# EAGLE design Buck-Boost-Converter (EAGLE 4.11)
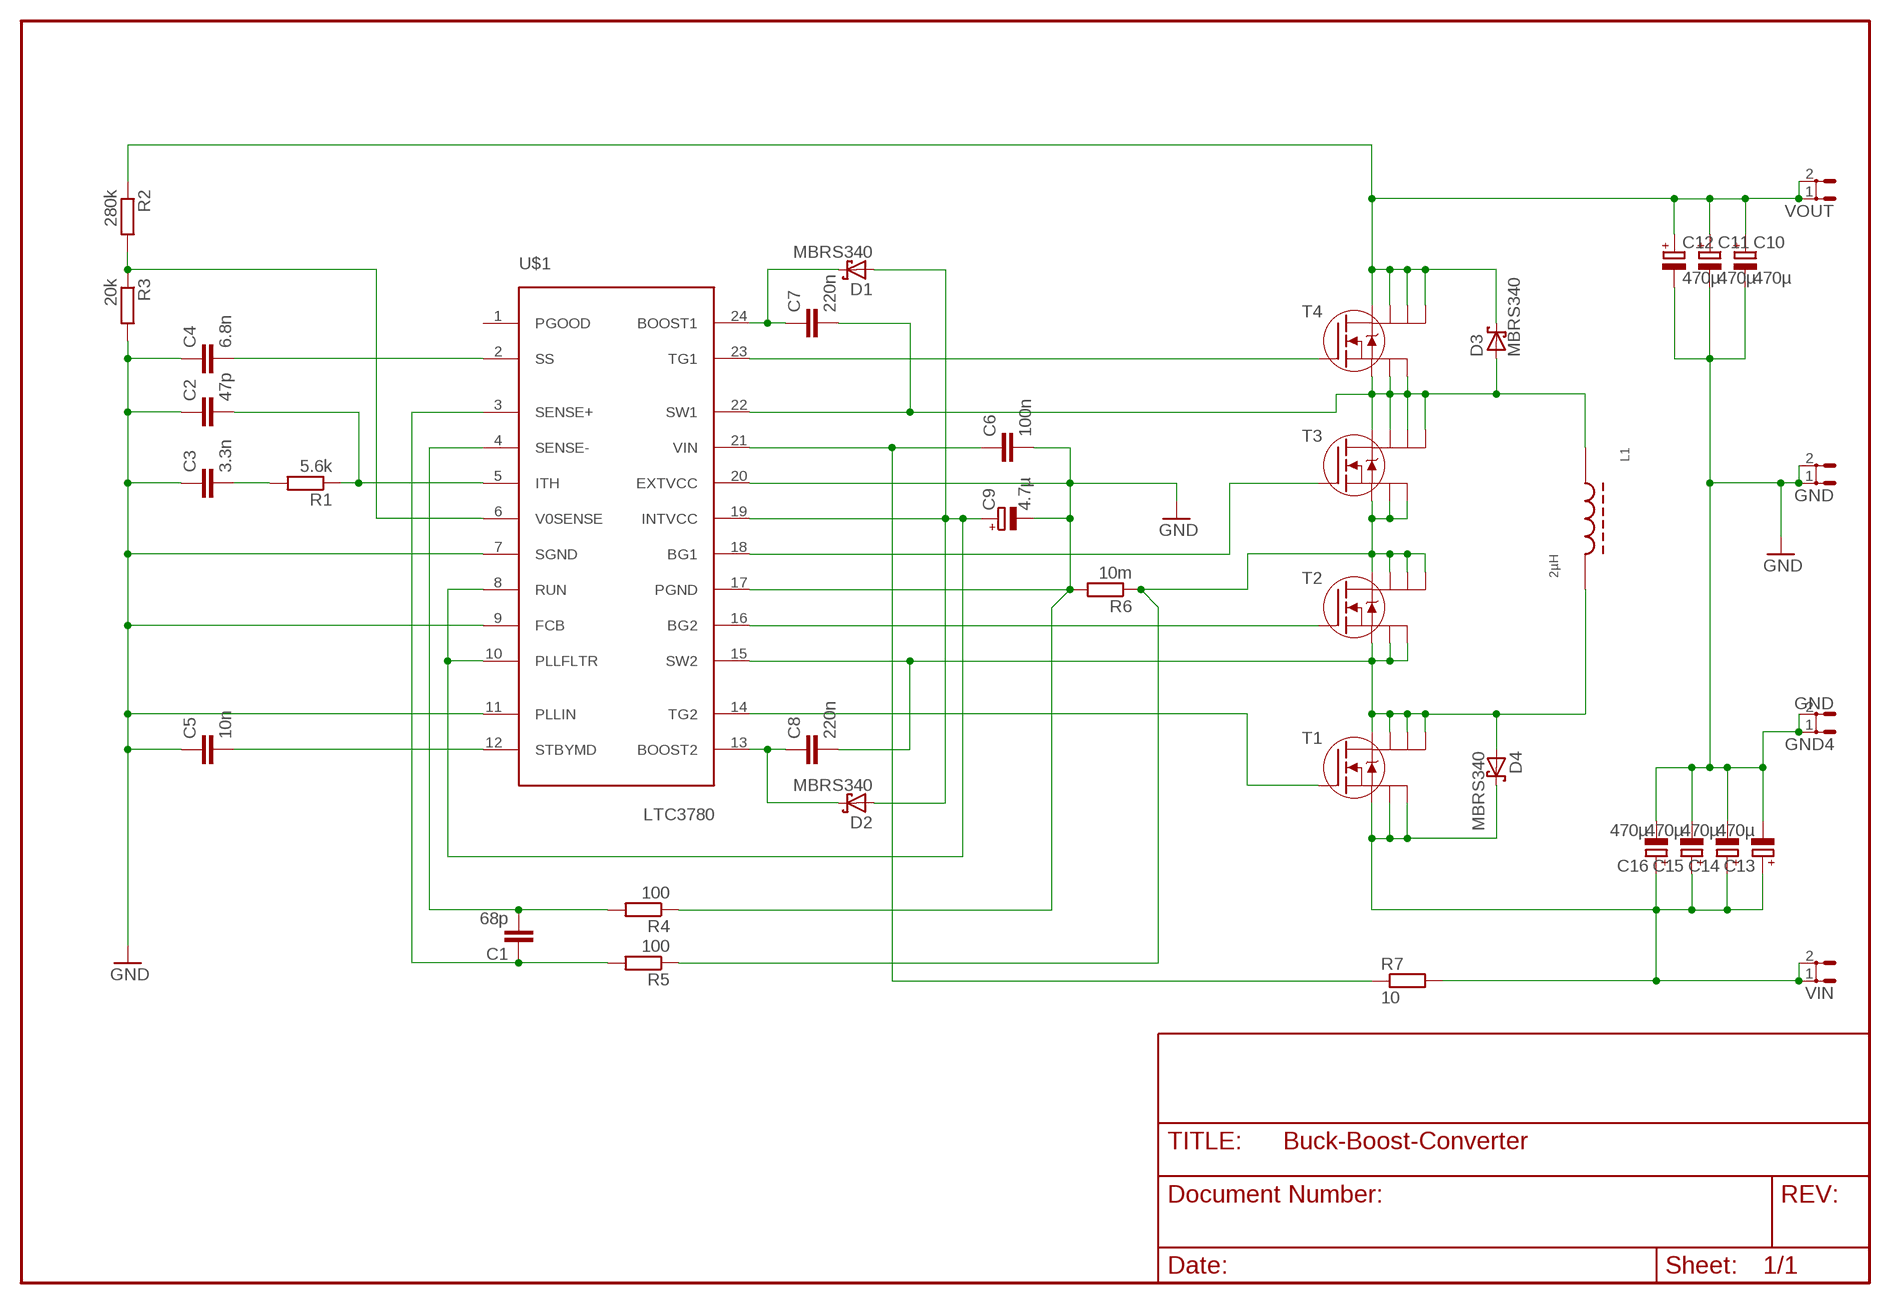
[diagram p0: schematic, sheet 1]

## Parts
C1  68p  C-EUC0805  [C0805]
C2  47p  C-EUC0805  [C0805]
C3  3.3n  C-EUC0805  [C0805]
C4  6.8n  C-EUC0805  [C0805]
C5  10n  C-EUC0805  [C0805]
C6  100n  C-EUC0805  [C0805]
C7  220n  C-EUC1812  [C1812]
C8  220n  C-EUC1812  [C1812]
C9  4.7µ  CPOL-EUD/7343-31R  [D/7343-31R]
C10  470µ  CPOL-EUE5-13  [E5-13]
C11  470µ  CPOL-EUE5-13  [E5-13]
C12  470µ  CPOL-EUE5-13  [E5-13]
C13  470µ  CPOL-EUE5-13  [E5-13]
C14  470µ  CPOL-EUE5-13  [E5-13]
C15  470µ  CPOL-EUE5-13  [E5-13]
C16  470µ  CPOL-EUE5-13  [E5-13]
D1  MBRS340  [SMC]
D2  MBRS340  [SMC]
D3  MBRS340  [SMC]
D4  MBRS340  [SMC]
GND  ST6,3  [ST6,3]
GND4  GND  ST6,3  [ST6,3]
L1  2µH  SER2000  [SER2000]
R1  5.6k  R-EU_R0805  [R0805]
R2  280k  R-EU_R0805  [R0805]
R3  20k  R-EU_R0805  [R0805]
R4  100  R-EU_R0805  [R0805]
R5  100  R-EU_R0805  [R0805]
R6  10m  R-EU_0207/7  [0207/7]
R7  10  R-EU_R1206  [R1206]
T1  IRF7413  [SO8-2]
T2  IRF7413  [SO8-2]
T3  IRF7413  [SO8-2]
T4  IRF7413  [SO8-2]
U$1  LTC3780  [SSOP24]
VIN  ST6,3  [ST6,3]
VOUT  ST6,3  [ST6,3]

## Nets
GND [Power]: C2.1 C3.1 C4.1 C5.1 C6.2 C9.- C10.- C11.- C12.- C13.- C14.- C15.- C16.- GND4.1 GND4.2 GND.1 GND.2 R3.2 R4.1 R6.2 U$1.7(SGND) U$1.9(FCB) U$1.11(PLLIN) U$1.17(PGND) U$1.20(EXTVCC)
N$1: T1.4(G) U$1.14(TG2)
N$2: T2.4(G) U$1.16(BG2)
N$3: T3.4(G) U$1.18(BG1)
N$4: T4.4(G) U$1.23(TG1)
N$5: C9.+ D1.A D2.A U$1.8(RUN) U$1.10(PLLFLTR) U$1.19(INTVCC)
N$7: C7.2 D3.A L1.1 T3.5(D) T3.6(D) T3.7(D) T3.8(D) T4.1(S) T4.2(S) T4.3(S) U$1.22(SW1)
N$8: C1.2 R4.2 U$1.4(SENSE-)
N$10: C1.1 R5.2 U$1.3(SENSE+)
N$11: C4.2 U$1.2(SS)
N$12: C2.2 R1.1 U$1.5(ITH)
N$13: C8.2 D4.A L1.2 T1.5(D) T1.6(D) T1.7(D) T1.8(D) T2.1(S) T2.2(S) T2.3(S) U$1.15(SW2)
N$14: C3.2 R1.2
N$15: R2.2 R3.1 U$1.6(V0SENSE)
N$16 [Power]: R5.1 R6.1 T2.5(D) T2.6(D) T2.7(D) T2.8(D) T3.1(S) T3.2(S) T3.3(S)
N$17: C7.1 D1.C U$1.24(BOOST1)
N$18: C5.2 U$1.12(STBYMD)
N$19: C8.1 D2.C U$1.13(BOOST2)
N$21: C6.1 R7.1 U$1.21(VIN)
N$22 [Power]: C10.+ C11.+ C12.+ D3.C R2.1 T4.5(D) T4.6(D) T4.7(D) T4.8(D) VOUT.1 VOUT.2
N$28: C13.+ C14.+ C15.+ C16.+ D4.C R7.2 T1.1(S) T1.2(S) T1.3(S) VIN.1 VIN.2
Unconnected: U$1.1(PGOOD)

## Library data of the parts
C1-C8 = rcl:C-EU: CAPACITOR, European symbol
C9-C16 = rcl:CPOL-EU: POLARIZED CAPACITOR, European symbol
D1-D4 = diode:MBRS340
GND GND4 VIN VOUT = con-rib:ST6,3: RIBBON CABLE CONNECTOR
L1 = inductor-coilcraft:SER2000: Unshieded Inductor
R1-R7 = rcl:R-EU_: RESISTOR, European symbol
T1-T4 = irf-2:IRF7413
U$1 = linear-technology:LTC3780: Buck-Boost-Controller High Efficiency, Synchrounous 4-Switch Buck-Boost-Controller

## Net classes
0 default: width 0.4 mm
1 Power: width 1.5 mm

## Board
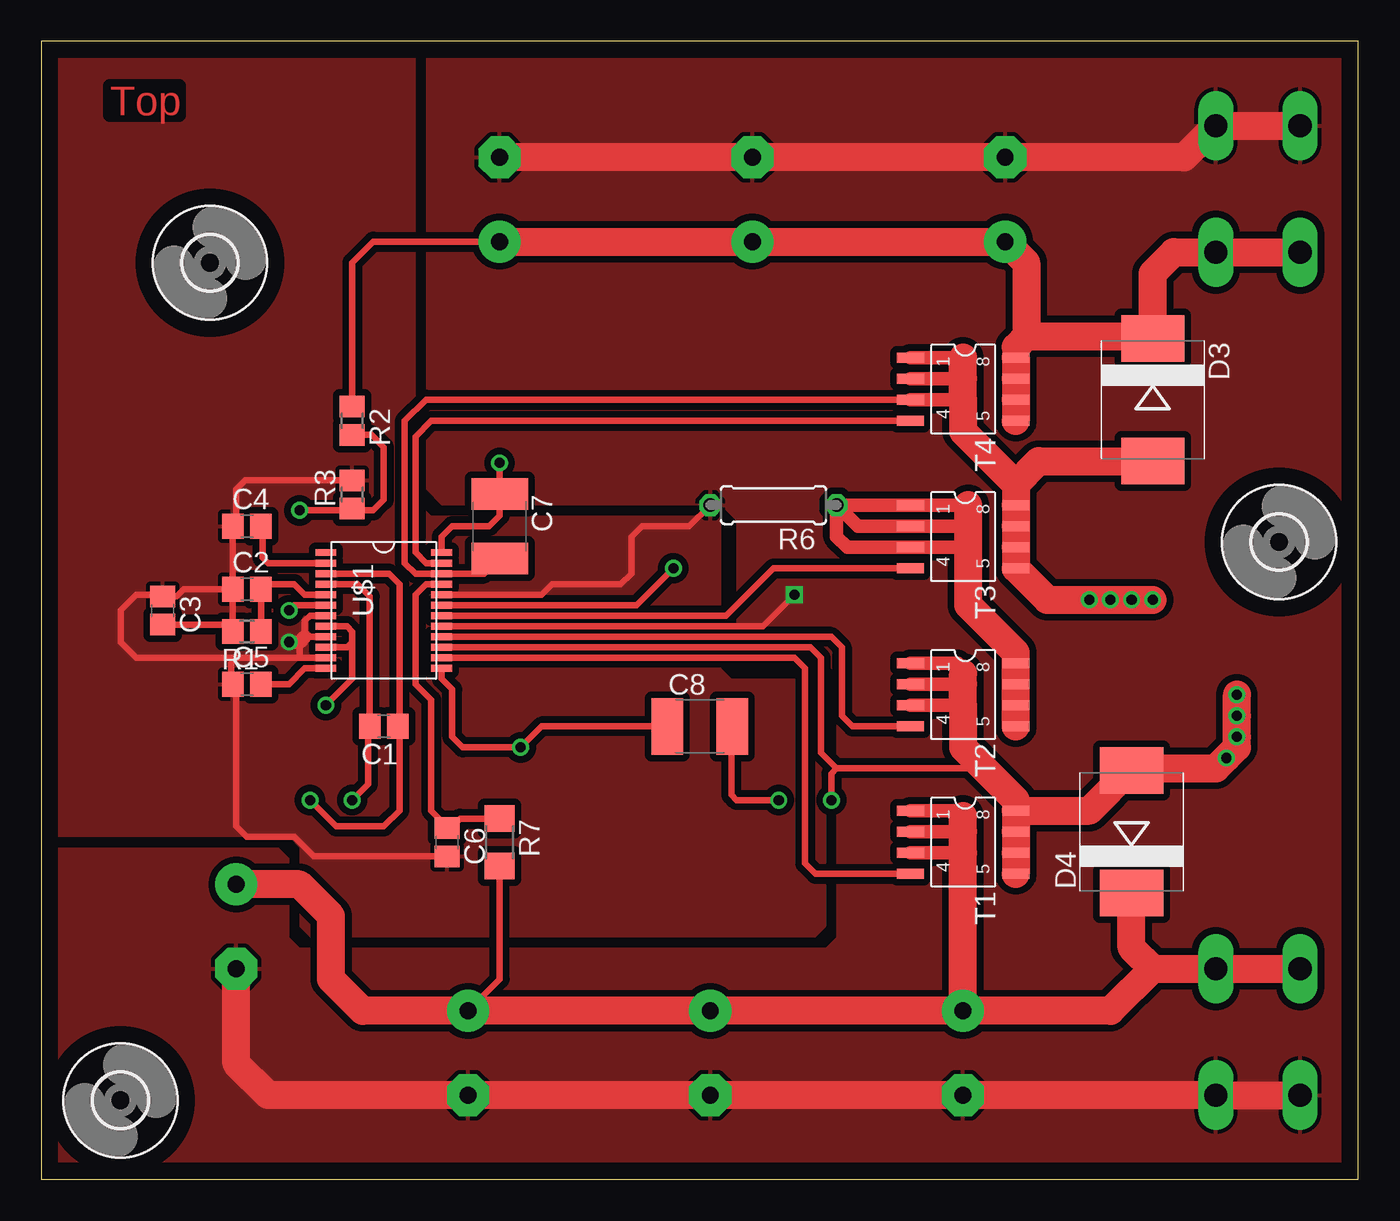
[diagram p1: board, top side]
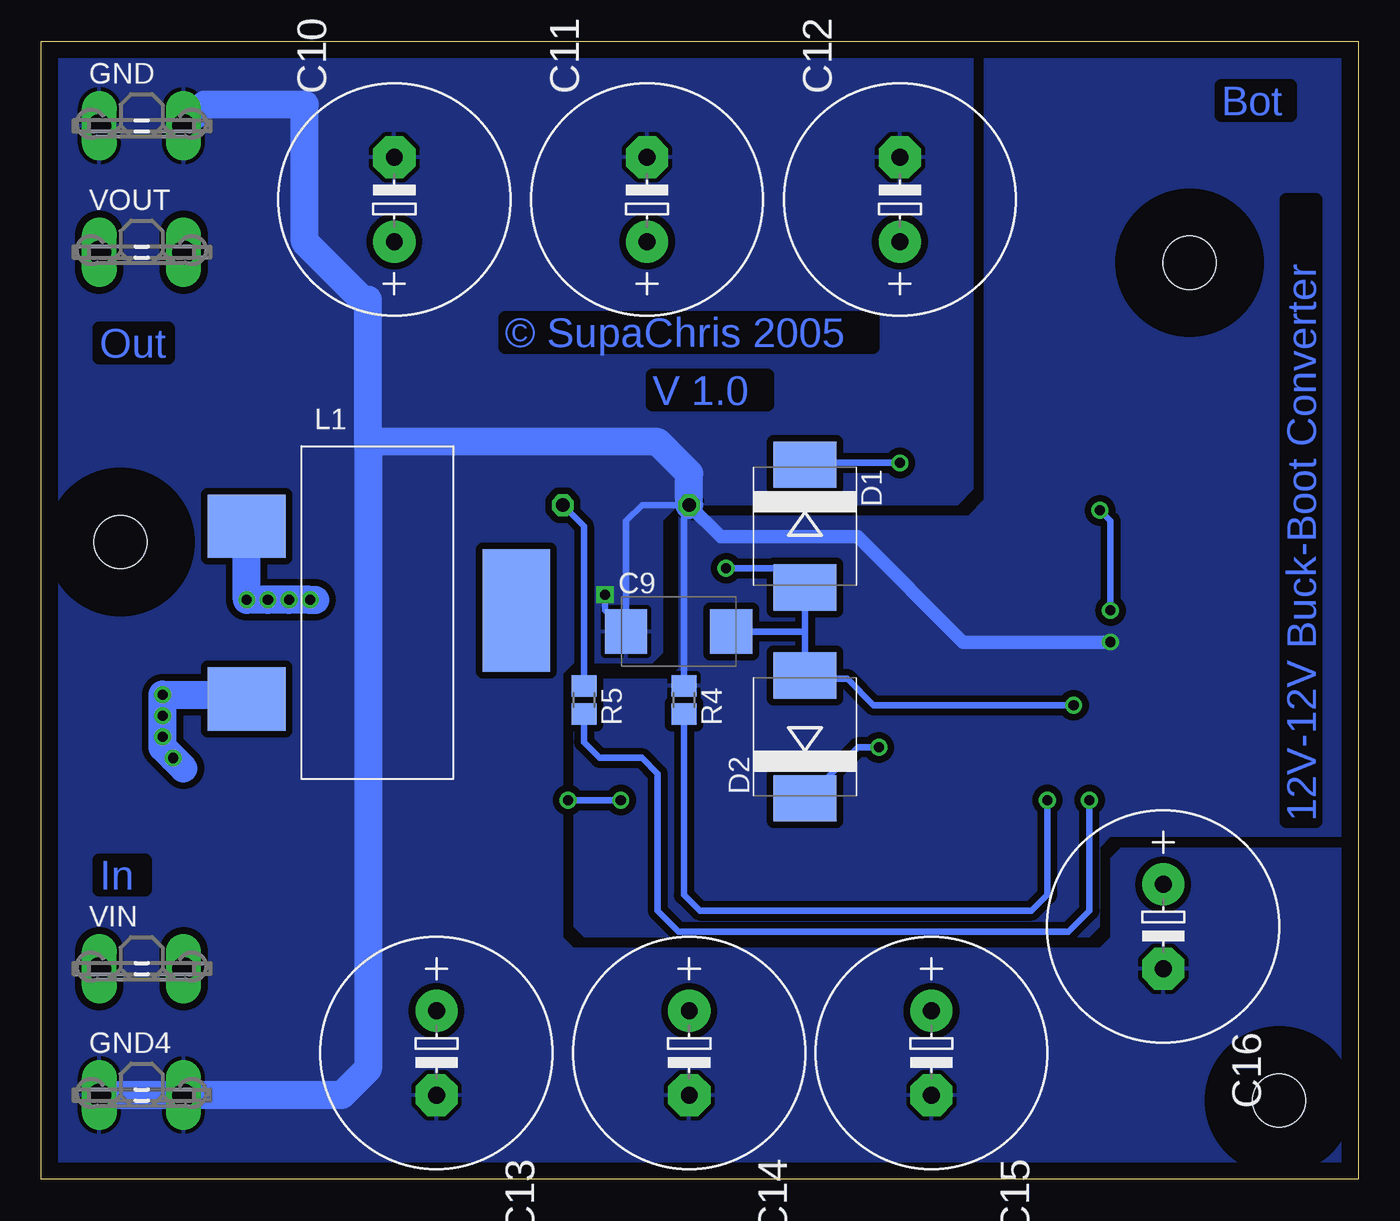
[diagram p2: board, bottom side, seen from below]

Size 79.38 x 68.58 mm. Coordinates in mm from the lower left corner, seen from the top.
Outline: 0,0 79.38,0 79.38,68.58 0,68.58 0,0
Copper layers (1+16): Top 0.035mm / dielectric 1.5mm / Bottom 0.035mm
Design rules "default": minimum track width 10mil, minimum drill 24mil, track to track 8mil, track to pad 8mil, pad to pad 8mil, via to via 8mil, smd to smd 8mil, copper to edge 40mil, drill to drill 8mil, minimum pad ring 10mil, minimum via ring 8mil, stop-mask expansion 4mil, vias tented up to drill 0mil, thermal gap 10mil

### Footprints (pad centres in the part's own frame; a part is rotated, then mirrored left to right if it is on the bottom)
C0805 = smd 1.3 x 1.5: 1 -0.85,0; 2 0.85,0
C1812 = smd 1.9 x 3.4: 1 -1.95,0; 2 1.95,0
D/7343-31R = smd 2.55 x 2.7: + 3.175,0; - -3.175,0
E5-13 = drill 1.016 pad 2.54 round: + -2.54,0 | drill 1.016 pad 2.54 octagon: - 2.54,0
SMC = smd 2.8 x 3.8: A 3.7,0; C -3.7,0
ST6,3 = drill 1.397 long: 1 -2.54,0; 2 2.54,0
SER2000 = smd 3.81 x 4.699: 1 0,0; 2 10.414,0 | smd 7.366 x 4.064: 3 5.08,16.256
R0805 = smd 1.3 x 1.5: 1 -0.85,0; 2 0.85,0
0207/7 = drill 0.813 octagon: 1 -3.81,0; 2 3.81,0
R1206 = smd 1.6 x 1.803: 1 -1.422,0; 2 1.422,0
SO8-2 = smd 0.61 x 1.626: 1 -2.54,-2.54; 2 -1.27,-2.54; 3 0,-2.54; 4 1.27,-2.54; 5 1.27,3.81; 6 0,3.81; 7 -1.27,3.81; 8 -2.54,3.81
SSOP24 = smd 0.42 x 1.25: 1 -3.493,-3.493; 2 -2.857,-3.493; 3 -2.223,-3.493; 4 -1.587,-3.493; 5 -0.953,-3.493; 6 -0.318,-3.493; 7 0.318,-3.493; 8 0.953,-3.493; 9 1.587,-3.493; 10 2.223,-3.493; 11 2.857,-3.493; 12 3.493,-3.493; 13 3.493,3.493; 14 2.857,3.493; 15 2.223,3.493; 16 1.587,3.493; 17 0.953,3.493; 18 0.318,3.493; 19 -0.318,3.493; 20 -0.953,3.493; 21 -1.587,3.493; 22 -2.223,3.493; 23 -2.857,3.493; 24 -3.493,3.493
3,2 = hole 3.2: 0,0

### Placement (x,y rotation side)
C1  20.64,27.3 180 top
C2  12.38,35.56 0 top
C3  7.3,34.29 270 top
C4  12.38,39.37 0 top
C5  12.38,29.84 0 top
C6  24.45,20.32 270 top
C7  27.62,39.37 270 top
C8  39.69,27.3 0 top
C9  40.96,33.02 0 bottom
C10  58.1,59.06 90 bottom
C11  42.86,59.06 90 bottom
C12  27.62,59.06 90 bottom
C13  55.56,7.62 270 bottom
C14  40.32,7.62 270 bottom
C15  25.72,7.62 270 bottom
C16  11.75,15.24 270 bottom
D1  33.34,39.37 270 bottom
D2  33.34,26.67 90 bottom
D3  66.99,46.99 270 top
D4  65.72,20.96 90 top
GND  73.34,63.5 0 bottom
GND4  73.34,5.08 0 bottom
L1  66.99,39.37 270 bottom
R1  12.38,33.02 180 top
R2  18.73,45.72 270 top
R3  18.73,41.28 90 top
R4  40.64,28.89 270 bottom
R5  46.67,28.89 270 bottom
R6  44.13,40.64 180 top
R7  27.62,20.32 270 top
T1  54.93,19.69 270 top
T2  54.93,28.58 270 top
T3  54.93,38.1 270 top
T4  54.93,46.99 270 top
U$1  20.64,34.29 270 top
U$2  [3,2]  10.16,55.25 0 top
U$3  [3,2]  4.76,4.76 0 top
U$4  [3,2]  74.61,38.42 0 top
VIN  73.34,12.7 0 bottom
VOUT  73.34,55.88 0 bottom

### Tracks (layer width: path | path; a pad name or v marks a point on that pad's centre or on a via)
GND  (via drill 0.61)
  Top 0.406: 11.43,33.02 11.53,33.12 C2.1 11.43,35.56 | 15.56,31.43 11.75,31.43 | 15.56,31.43 U$1.11 | 11.75,31.43 11.43,31.12 11.43,29.84 C5.1 11.75,29.84 11.75,21.27 12.38,20.64 15.24,20.64 16.41,19.47 C6.2 | 11.43,35.56 8.57,35.56 8.15,35.14 C3.1 7.3,35.24 5.72,35.24 4.76,34.29 4.76,32.39 5.72,31.43 11.75,31.43 | U$1.7 16.19,33.97 15.87,33.66 15.87,33.02 16.19,32.7 U$1.9 15.87,32.7 | 15.56,32.39 15.56,31.43 | 11.43,35.56 11.53,35.66 C4.1 11.75,39.37 11.75,41.59 12.28,42.12 R3.2 | U$1.17 43.5,33.34 v45.4,35.24 | U$1.20 30.16,35.24 30.8,35.88 34.93,35.88 35.56,36.51 35.56,38.73 36.19,39.37 39.05,39.37 R6.2
  Top 0.813: v14.92,32.39 15.56,32.39 15.87,32.7
  Top 1.676: GND4.1 GND4.2 C13.- C14.- C15.- 13.65,5.08 11.75,6.99 C16.- | C12.- C11.- C10.- 68.9,61.59 GND.2 GND.1
  Bottom 0.406: 44.13,33.34 C9.- 45.4,34.29 v45.4,35.24 | 44.13,33.34 43.82,33.02 | 44.13,33.34 44.13,39.69 43.18,40.64 R6.2 40.64,40.32 R4.1
  Bottom 0.813: v14.92,32.39 23.81,32.39 30.16,38.73 38.42,38.73 R6.2
  Bottom 1.676: GND.2 69.53,64.77 63.5,64.77 63.5,56.52 60.01,53.02 59.69,53.02 59.69,44.45 | 59.69,44.45 59.69,6.67 61.28,5.08 GND4.2 GND4.1 | R6.2 40.32,42.55 42.23,44.45 59.69,44.45
  pour Bottom (isolate 0.406): 79.38,68.58 23.18,68.58 23.18,41.59 24.13,40.64 40.96,40.64 41.91,39.69 41.91,31.75 42.55,31.12 47.31,31.12 47.94,30.48 47.94,14.61 47.31,13.97 15.56,13.97 14.92,14.61 14.92,19.37 14.29,20 0,20 0,0 79.38,0
  pour Top (isolate 0.406): 79.38,68.58 23.18,68.58 23.18,41.59 24.13,40.64 40.96,40.64 41.91,39.69 41.91,31.75 42.55,31.12 47.31,31.12 47.94,30.48 47.94,14.61 47.31,13.97 15.56,13.97 14.92,14.61 14.92,19.37 14.29,20 0,20 0,0 79.38,0
  pour Top (isolate 0.406): 0,68.58 22.54,68.58 22.54,40.96 23.5,40.01 40.96,40.01 40.96,30.8 41.59,30.16 46.67,30.16 47.31,29.53 47.31,15.24 46.67,14.61 16.19,14.61 15.56,15.24 15.56,20 14.92,20.64 0,20.64
  pour Bottom (isolate 0.406): 0,68.58 22.54,68.58 22.54,68.26 22.54,40.96 23.5,40.01 40.96,40.01 40.96,30.8 41.59,30.16 46.67,30.16 47.31,29.53 47.31,15.24 46.67,14.61 16.19,14.61 15.56,15.24 15.56,20 14.92,20.64 0,20.64
N$1
  Top 0.406: U$1.14 45.4,31.43 46.04,30.8 46.04,19.05 46.67,18.41 T1.4
N$2
  Top 0.406: U$1.16 47.62,32.7 48.26,32.07 48.26,27.94 48.89,27.3 T2.4
N$3
  Top 0.406: T3.4 44.13,36.83 41.28,33.97 U$1.18
N$4
  Top 0.406: U$1.23 23.18,37.15 22.54,37.78 22.54,44.77 23.5,45.72 T4.4
N$5  (via drill 0.61)
  Top 0.406: U$1.8 18.42,33.34 18.73,33.02 | 18.73,33.02 18.73,32.39 18.42,32.07 U$1.10 | U$1.19 35.88,34.61 v38.1,36.83 | 18.73,33.02 18.73,30.16 v17.15,28.58
  Bottom 0.406: 33.34,35.56 33.34,33.02 | 33.34,35.56 D1.A | 33.34,33.02 D2.A 33.34,30.16 30.8,30.16 29.21,28.58 v17.15,28.58 | 33.34,33.02 C9.+ | v38.1,36.83 34.61,36.83 33.34,35.56
N$7  (via drill 0.61)
  Top 0.406: 55.56,49.53 55.09,48.1 55.88,48.26 | T4.3 23.18,46.99 21.91,45.72 21.91,37.15 22.54,36.51 U$1.22 26.67,36.51 27.62,37.47 C7.2
  Top 0.813: 55.56,49.53 T4.1 | 55.56,48.26 T4.2 | T4.3 55.56,46.99
  Top 1.676: 58.74,41.91 T3.8 T3.7 T3.6 T3.5 60.64,34.93 v63.18,34.93 v64.45,34.93 v65.72,34.93 v66.99,34.93 | 58.74,41.91 55.56,45.09 55.56,46.99 55.56,48.26 55.56,49.53 | D3.A 60.12,43.29 58.74,41.91
  Bottom 1.676: L1.1 v66.99,34.93 v65.72,34.93 v64.45,34.93 v63.18,34.93 62.86,34.93
N$8  (via drill 0.61)
  Top 0.406: U$1.4 19.05,35.88 19.79,35.14 C1.2 19.68,27.3 19.68,23.81 v18.73,22.86
  Bottom 0.406: v18.73,22.86 18.73,17.15 19.68,16.19 39.69,16.19 40.64,17.15 R4.2
N$10  (via drill 0.61)
  Top 0.406: U$1.3 20.95,36.51 21.59,35.88 21.59,27.3 | 21.59,27.3 C1.1 | 21.59,27.3 21.59,22.23 20.64,21.27 17.78,21.27 v16.19,22.86
  Bottom 0.406: v16.19,22.86 16.19,16.19 17.46,14.92 40.96,14.92 42.23,16.19 42.23,24.45 43.18,25.4 45.72,25.4 46.67,26.35 R5.2
N$11
  Top 0.406: U$1.2 13.65,37.15 13.34,37.47 13.34,39.37 C4.2
N$12
  Top 0.406: 13.34,35.56 C2.2 13.23,33.23 13.02,33.02 R1.1 | 13.34,35.56 13.65,35.24 | U$1.5 15.87,35.24 15.24,35.88 13.65,35.88 13.34,35.56
N$13  (via drill 0.61)
  Top 0.406: 65.72,24.77 D4.A | 58.74,22.86 T1.8 | U$1.15 46.36,32.07 46.99,31.43 46.99,25.72 47.94,24.77 | 56.83,24.77 47.94,24.77 | v47.62,22.86 47.62,24.45 47.94,24.77 | v44.45,22.86 41.91,22.86 41.59,23.18 41.59,27.3 C8.2
  Top 0.813: 55.56,30.48 55.56,30.8 55.25,31.12 T2.1 | 55.56,29.84 T2.2 | T2.3 55.56,28.58
  Top 1.676: T1.5 T1.6 T1.7 T1.8 63.18,22.23 65.72,24.77 70.8,24.77 v71.44,25.4 72.07,26.04 v72.07,26.67 v72.07,27.94 v72.07,29.21 | 58.74,22.86 56.83,24.77 55.56,26.04 55.56,28.58 55.56,29.84 55.56,30.48
  Bottom 0.406: 66.99,29.21 L1.2 | v47.62,22.86 v44.45,22.86
  Bottom 1.676: 66.99,29.21 v72.07,29.21 v72.07,27.94 v72.07,26.67 72.07,26.04 v71.44,25.4 70.8,24.77
N$14
  Top 0.406: R1.2 11.75,33.02 11.33,33.44 C3.2
N$15  (via drill 0.61)
  Top 0.406: R2.2 19.9,44.87 20.64,44.13 20.64,40.96 20,40.32 18.73,40.32 | 18.73,40.32 R3.1 | U$1.6 15.24,34.61 v14.92,34.29 | 18.73,40.32 v15.56,40.32
  Bottom 0.406: v14.92,34.29 14.92,39.69 v15.56,40.32
N$16
  Top 0.813: R6.1 T3.1 55.88,40.64 | 55.88,39.37 52.71,39.37 | 52.71,39.37 T3.2 | 55.88,38.1 52.71,38.1 | 52.71,38.1 T3.3 | 52.71,39.37 49.21,39.37 R6.1 | 52.71,38.1 48.58,38.1 47.94,38.73 R6.1
  Top 1.676: T2.5 T2.6 T2.7 T2.8 58.74,31.75 55.88,34.61 55.88,38.1 55.88,39.37 55.88,40.64
  Bottom 0.406: R6.1 46.67,39.37 R5.1
N$17  (via drill 0.61)
  Top 0.406: v27.62,43.18 C7.1 27.62,40.01 26.99,39.37 24.76,39.37 24.13,38.73 U$1.24
  Bottom 0.406: D1.C 33.34,43.18 v27.62,43.18
N$18
  Top 0.406: C5.2 14.92,29.84 15.87,30.8 U$1.12
N$19  (via drill 0.61)
  Top 0.406: U$1.13 24.13,30.16 24.76,29.53 24.76,26.67 25.4,26.04 v28.89,26.04 30.16,27.3 C8.1
  Bottom 0.406: D2.C 33.34,22.86 30.16,26.04 v28.89,26.04
N$21
  Top 0.406: C6.1 24.45,20.96 24.61,21.11 | R7.1 25.23,21.74 24.61,21.11 | U$1.21 23.18,35.88 22.54,35.24 22.54,29.84 23.5,28.89 23.5,22.23 24.61,21.11 | 24.61,21.11
N$22
  Top 0.406: 58.74,50.16 T4.8 | 66.99,50.8 D3.C | C12.+ 20,56.52 18.73,55.25 R2.1 18.73,46.36
  Top 1.676: T4.5 T4.6 T4.7 T4.8 | 59.37,50.8 58.74,50.16 | 59.37,50.8 66.99,50.8 66.99,54.61 68.26,55.88 VOUT.2 VOUT.1 | C12.+ C11.+ C10.+ 59.37,55.25 59.37,50.8
N$28
  Top 0.406: C15.+ 27.62,12.06 R7.2 27.62,19.05
  Top 0.813: 55.56,21.91 55.56,22.23 T1.1 | 55.56,20.96 T1.2 | 55.56,19.69 T1.3
  Top 1.676: C13.+ C14.+ C15.+ 19.37,10.16 17.46,12.06 17.46,15.88 15.56,17.78 C16.+ | VIN.1 VIN.2 66.99,12.7 | 66.99,12.7 65.72,13.97 D4.C | C13.+ 64.45,10.16 66.99,12.7 | C13.+ 55.56,19.69 55.56,20.96 55.56,21.91

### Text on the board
Top: Top
Bottom: Bot | © SupaChris 2005 | Out | V 1.0 | 12V-12V Buck-Boot Converter | In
